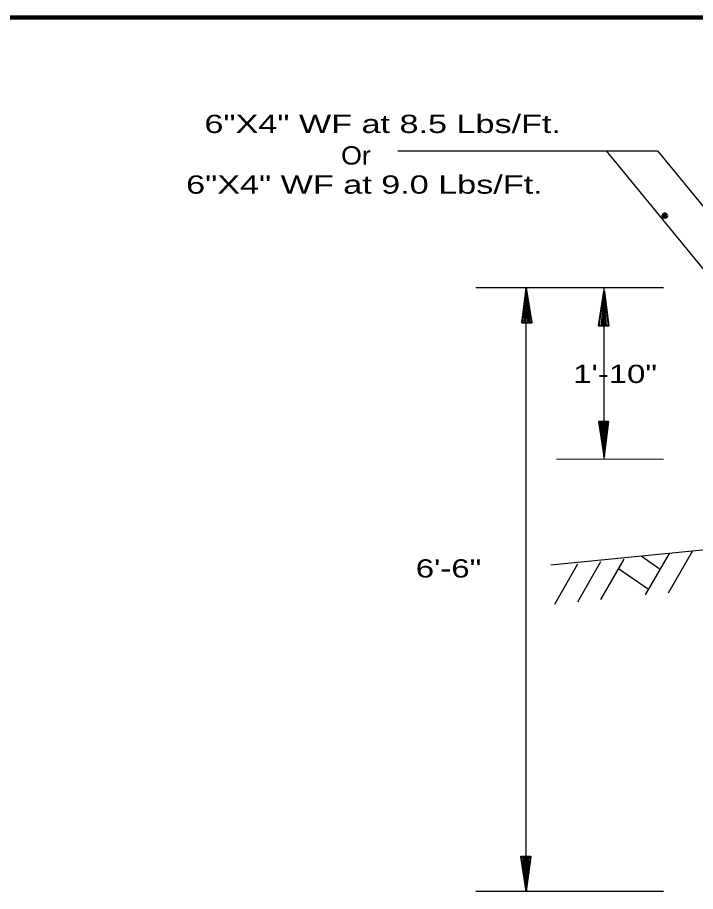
# Model space of a CAD drawing. Extents: x 856.9 to 891.7, y -2278.5 to -2254.7.
# Drawn here: x 868.03 to 872.81, y -2262.33 to -2256.16 of the extents above; entities that cross this region are included whole.
import ezdxf

# ---------------------------------------------------------------- set-up
doc = ezdxf.new("R2010")
doc.units = 0
doc.header["$LTSCALE"] = 0.051
doc.header["$PDMODE"] = 32
doc.header["$PDSIZE"] = 0.0255
doc.layers.add('1', color=7, linetype='Continuous', lineweight=70)
doc.layers.add('3', color=7, linetype='Continuous', lineweight=40)

msp = doc.modelspace()

# ---------------------------------------------------------------- linework, layer by layer
at = {"layer": '1', "lineweight": 25}
for p, q in [((870.71, -2257.10383), (872.54325, -2257.10383)), ((872.18025, -2257.10383), (872.97158, -2258.06958)), ((872.54325, -2257.10383), (873.33458, -2258.06958)), ((872.5855, -2258.06908), (871.2605, -2258.06908)), ((871.61675, -2262.32542), (871.61675, -2258.06833)), ((872.166, -2259.27808), (872.166, -2258.06908)), ((874.51683, -2259.75225), (871.78975, -2260.02467)), ((872.45708, -2260.23425), (872.62675, -2259.94158)), ((872.62017, -2260.21858), (872.78917, -2259.92517)), ((871.97967, -2260.28208), (872.14342, -2259.9985)), ((872.14275, -2260.26567), (872.30633, -2259.98208)), ((872.5605, -2260.05475), (872.427, -2259.96117)), ((871.81725, -2260.29842), (871.981, -2260.01492)), ((872.47867, -2260.197), (872.26783, -2260.04958)), ((872.5855, -2262.32425), (871.2605, -2262.32425))]:
    msp.add_line(p, q, dxfattribs=at)
at = {"layer": '1', "lineweight": 13}
msp.add_line((872.5855, -2259.27808), (871.82908, -2259.27808), dxfattribs=at)
at = {"layer": '1', "lineweight": 40}
for points in [[(871.61675, -2258.06833), (871.58533, -2258.31267), (871.65542, -2258.31267)], [(872.166, -2258.09317), (872.1975, -2258.33733), (872.12733, -2258.33733)], [(872.166, -2259.25833), (872.1975, -2259.01417), (872.12733, -2259.01417)], [(871.61675, -2262.32542), (871.64825, -2262.08125), (871.57808, -2262.08125)]]:
    msp.add_lwpolyline(points, close=True, dxfattribs=at)
for points in [[(871.60308, -2258.31267), (871.61675, -2258.12917), (871.63767, -2258.31267)], [(872.17975, -2258.33733), (872.166, -2258.154), (872.14508, -2258.33733)], [(871.6115, -2258.31267), (871.61867, -2258.22558), (871.62933, -2258.31267)], [(872.17117, -2258.33733), (872.16408, -2258.25025), (872.1535, -2258.33733)], [(872.17975, -2259.01417), (872.166, -2259.1975), (872.14508, -2259.01417)], [(872.17117, -2259.01417), (872.16408, -2259.10125), (872.1535, -2259.01417)], [(871.6305, -2262.08125), (871.61675, -2262.26458), (871.59583, -2262.08125)], [(871.62192, -2262.08125), (871.61483, -2262.16833), (871.60425, -2262.08125)]]:
    msp.add_lwpolyline(points, dxfattribs=at)
at = {"layer": '1'}
msp.add_point((872.59325, -2257.56133), dxfattribs=at)
at = {"layer": '3', "lineweight": 158}
msp.add_line((891.2, -2256.16333), (858.7, -2256.16333), dxfattribs=at)

# ---------------------------------------------------------------- texts
at = {"layer": '1'}
for s, height, width, p in [('6"X4" WF at 8.5 Lbs/Ft.', 0.1287, 1.4, (869.34625, -2256.97783)), ('Or', 0.1287, 1.1, (870.30975, -2257.20008)), ('6"X4" WF at 9.0 Lbs/Ft.', 0.1287, 1.4, (869.21708, -2257.4055)), ('1\'-10"', 0.1286, 1.35, (871.9475, -2258.74033)), ('6\'-6"', 0.1286, 1.35, (870.837, -2260.11175))]:
    msp.add_text(s, height=height, dxfattribs=dict(at, width=width)).set_placement(p)

doc.saveas('drawing.dxf')
